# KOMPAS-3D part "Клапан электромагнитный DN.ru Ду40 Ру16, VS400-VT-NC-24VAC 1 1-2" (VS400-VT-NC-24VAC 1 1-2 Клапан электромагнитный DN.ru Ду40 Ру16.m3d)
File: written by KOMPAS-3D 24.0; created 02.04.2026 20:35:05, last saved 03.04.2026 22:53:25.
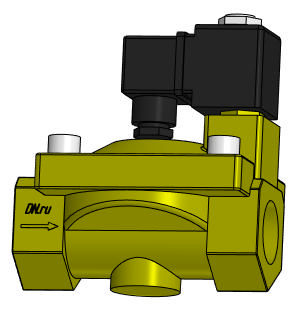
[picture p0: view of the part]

Document properties: Автор: artio; Полное имя файла: C:\Users\artio\OneDrive\Рабочий стол\Клапан электромагнитный DN.ru\VS400-VT-NC\VS400-VT-NC-24VAC 1 1-2 Клапан электромагнитный DN.ru Ду40 Ру16.m3d

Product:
- Body: Тело 1  | qty 1
    Масса: 4.144257
- Part/product: Клапан электромагнитный DN.ru Ду40 Ру16  | designation VS400-VT-NC-24VAC 1 1-2
    Масса: 2.321
    Раздел спецификации: Прочие изделия
    Примечание: D130-05501
    additional columns: ef56311e-7521-43dc-8291-0e6108b3d81d; VS400-ET-NC-220VAC 1 1-2; artio; c; Шероховатость не задана; Да

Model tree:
1. Операция без истории:1

Expressions: VS400-VT-NC-24VAC 1 1-2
